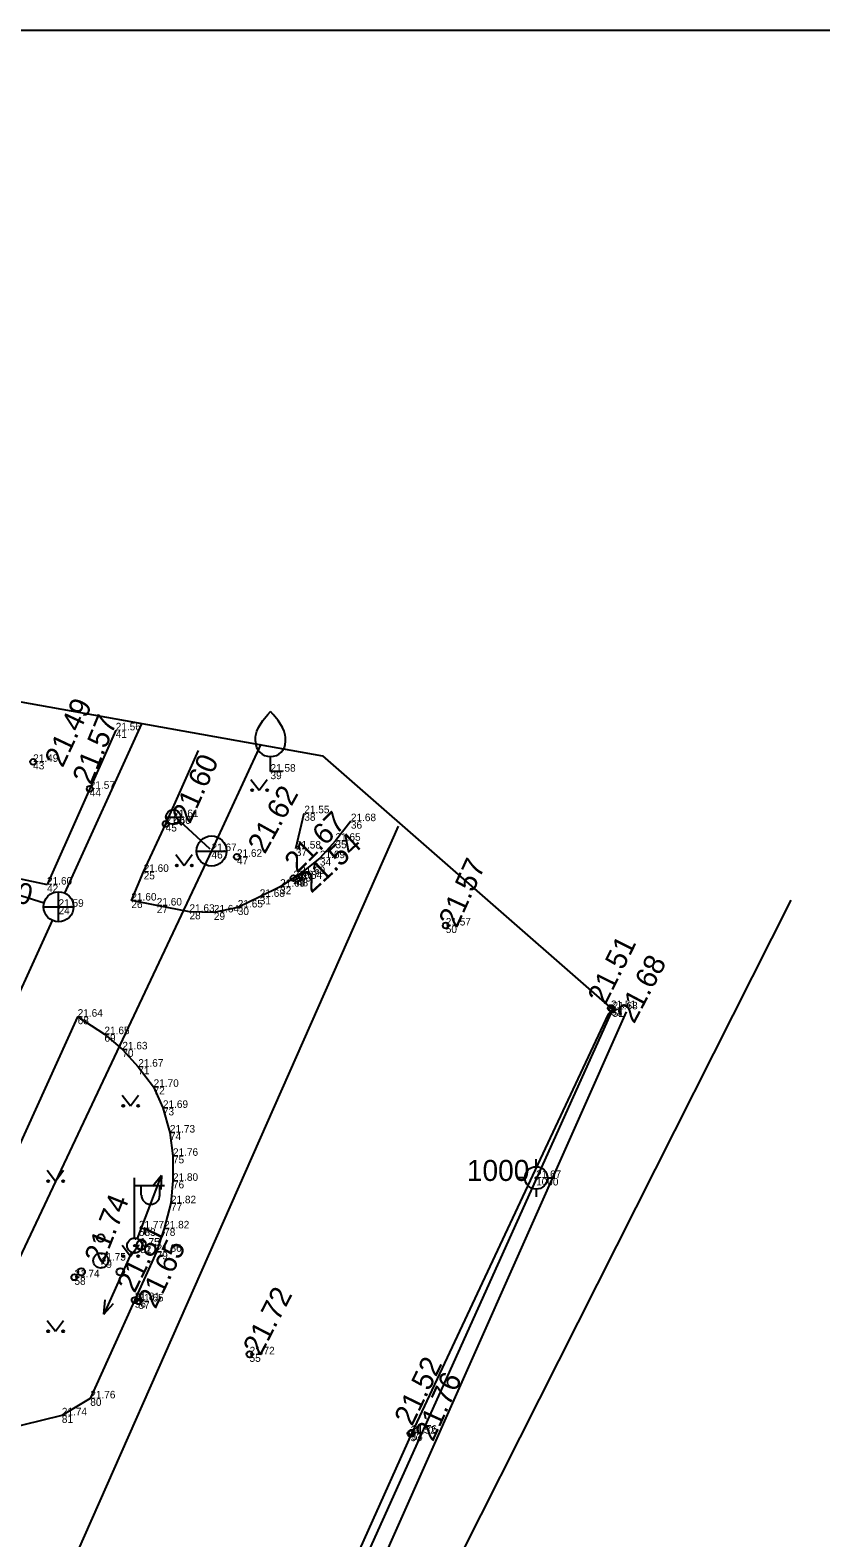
# Model space of a CAD drawing. Extents: x 714279 to 714471, y 6589851 to 6590083.
# Drawn here: x 714408.7 to 714435, y 6590021.5 to 6590071.6 of the extents above; entities that cross this region are included whole.
import ezdxf

# ---------------------------------------------------------------- set-up
doc = ezdxf.new("R2010")
doc.units = 0
for name, color, linetype in [('ALUSVORK', 7, 'Continuous'), ('HALJASTUS', 7, 'Continuous'), ('KKAEV', 7, 'Continuous'), ('KORGUS', 7, 'Continuous'), ('KPKAABEL', 7, 'Continuous'), ('KTRASS', 7, 'Continuous'), ('MOOTKORG', 7, 'Continuous'), ('MOOTMPUNKT', 7, 'Continuous'), ('MOOTPIIR', 7, 'Continuous'), ('MPOHULIIN', 7, 'Continuous'), ('POST', 7, 'Continuous'), ('PUU', 7, 'Continuous'), ('SKTRASS', 7, 'Continuous'), ('TEE', 7, 'Continuous'), ('VKAEV', 7, 'Continuous'), ('VORMISTUS', 7, 'Continuous'), ('VTRASS', 7, 'Continuous')]:
    doc.layers.add(name, color=color, linetype=linetype)

# ---------------------------------------------------------------- blocks, each defined once
blk = doc.blocks.new('KAKAEV')
at = {"layer": 'KKAEV'}
for p, q in [((-1, 0), (1, 0)), ((0, -1), (0, 1))]:
    blk.add_line(p, q, dxfattribs=at)
blk.add_circle((0, 0), 1, dxfattribs=at)
blk = doc.blocks.new('VILJA1')
at = {"layer": 'PUU'}
for p, q in [((0, 0), (0, 1)), ((0.8, 0), (0, 0))]:
    blk.add_line(p, q, dxfattribs=at)
for points in [[(-1, 2), (-1, 2.3), (-0.98, 2.43), (-0.91, 2.69), (-0.79, 2.93), (-0.5, 3.4), (-0.18, 3.81), (0, 4)], [(1, 2), (1, 2.3), (0.98, 2.43), (0.91, 2.69), (0.79, 2.93), (0.5, 3.4), (0.18, 3.81), (0, 4)]]:
    blk.add_lwpolyline(points, dxfattribs=at)
blk.add_arc((0, 2), 1, 180, 0, dxfattribs=at)
blk = doc.blocks.new('VESIIB')
at = {"layer": 'VKAEV'}
for p, q in [((-0.7, 0), (0.7, 0)), ((-0.49, -0.49), (-0.77, -0.77)), ((0.49, -0.49), (0.77, -0.77))]:
    blk.add_line(p, q, dxfattribs=at)
blk.add_circle((0, 0), 0.7, dxfattribs=at)
blk = doc.blocks.new('RING02')
at = {"layer": 'KORGUS'}
blk.add_circle((0, 0), 0.2, dxfattribs=at)
blk = doc.blocks.new('RING02_1')
at = {"layer": 'KORGUS'}
blk.add_circle((0, 0), 0.2, dxfattribs=at)
blk = doc.blocks.new('RING02_2')
at = {"layer": 'KORGUS'}
blk.add_circle((0, 0), 0.2, dxfattribs=at)
blk = doc.blocks.new('PQQSAS')
at = {"layer": 'HALJASTUS'}
for centre, radius in [((0, 1.5), 0.25), ((0, 0), 0.5), ((-1.3, -0.75), 0.25), ((1.3, -0.75), 0.25)]:
    blk.add_circle(centre, radius, dxfattribs=at)
blk = doc.blocks.new('SPYMAR')
at = {"layer": 'ALUSVORK'}
for p, q in [((0, 0.75), (0, 1.25)), ((-0.75, 0), (-1.25, 0)), ((0.75, 0), (1.25, 0)), ((0, -0.75), (0, -1.25))]:
    blk.add_line(p, q, dxfattribs=at)
for radius in [0.75, 0.044]:
    blk.add_circle((0, 0), radius, dxfattribs=at)
blk = doc.blocks.new('BEPOST')
at = {"layer": 'POST'}
for radius in [0.5, 0.0467]:
    blk.add_circle((0, 0), radius, dxfattribs=at)
blk = doc.blocks.new('POINT_DISPLAY')
blk.add_line((0, 0), (0, 0))
blk = doc.blocks.new('VAPOST')
at = {"layer": 'POST'}
for p, q in [((0, 0.5), (0, 4.5)), ((0, 4), (2, 4)), ((0.45, 3.36), (0.45, 4)), ((1.68, 3.36), (1.68, 4))]:
    blk.add_line(p, q, dxfattribs=at)
blk.add_arc((1.07, 3.36), 0.613, 180, 0, dxfattribs=at)
blk.add_blockref('POINT_DISPLAY', (0, 0), dxfattribs=at)
blk = doc.blocks.new('MPSUUN')
at = {"layer": 'MPOHULIIN'}
for p, q in [((0.5, 0), (5, 0)), ((5, 0), (4.1, 0.3)), ((5, 0), (4.1, -0.3))]:
    blk.add_line(p, q, dxfattribs=at)
blk.add_blockref('POINT_DISPLAY', (0, 0), dxfattribs=at)
blk = doc.blocks.new('VEKAEV')
at = {"layer": 'VKAEV'}
blk.add_line((-1, 0), (1, 0), dxfattribs=at)
blk.add_circle((0, 0), 1, dxfattribs=at)
blk = doc.blocks.new('MURU_1')
at = {"layer": 'HALJASTUS'}
for p, q in [((-0.93, 1.21), (0, 0)), ((0, 0), (0.89, 1.21))]:
    blk.add_line(p, q, dxfattribs=at)
for centre in [(-0.8, 0), (0.86, 0)]:
    blk.add_circle(centre, 0.11, dxfattribs=at)

msp = doc.modelspace()

# ---------------------------------------------------------------- linework, layer by layer
at = {"layer": 'HALJASTUS'}
msp.add_lwpolyline([(714417.521, 6590044.411), (714417.803, 6590045.585)], dxfattribs=at)
at = {"layer": 'KPKAABEL'}
msp.add_lwpolyline([(714396.776, 6589958.555), (714410.513, 6589990.138), (714421.117, 6590017.14), (714434.01, 6590042.696)], dxfattribs=at)
at = {"layer": 'KTRASS'}
for points in [[(714409.141, 6590042.598), (714389.491, 6590048.747)], [(714409.831, 6590042.928), (714412.393, 6590048.562)], [(714399.928, 6590021.168), (714409.418, 6590042.018)]]:
    msp.add_lwpolyline(points, dxfattribs=at)
at = {"layer": 'MOOTPIIR'}
msp.add_lwpolyline([(714325.392, 6590064.148), (714418.405, 6590047.495), (714428.059, 6590039.059), (714392.952, 6589961.13), (714372.822, 6589966.903), (714302.696, 6589965.199), (714319.941, 6590042.637), (714325.392, 6590064.148)], dxfattribs=at)
at = {"layer": 'SKTRASS'}
msp.add_lwpolyline([(714419.795, 6590019.325), (714428.522, 6590038.973)], dxfattribs=at)
at = {"layer": 'TEE'}
for points in [[(714333.617, 6590059.437), (714358.94, 6590054.148), (714385.625, 6590048.292), (714406.584, 6590043.775), (714409.241, 6590043.211)], [(714411.528, 6590048.344), (714409.241, 6590043.211)], [(714419.354, 6590045.322), (714418.84, 6590044.67), (714418.323, 6590044.091), (714417.66, 6590043.564), (714416.998, 6590043.14), (714416.32, 6590042.803), (714415.589, 6590042.45), (714414.793, 6590042.284), (714413.981, 6590042.306), (714412.893, 6590042.515), (714412.048, 6590042.68), (714412.457, 6590043.635), (714413.19, 6590045.228), (714414.282, 6590047.669)], [(714428.059, 6590039.059), (714427.912, 6590038.899), (714421.383, 6590024.973), (714411.21, 6590002.295), (714399.51, 6589976.749), (714392.577, 6589961.261), (714392.577, 6589961.261)], [(714404.084, 6590024.922), (714404.084, 6590024.922), (714406.869, 6590031.347), (714410.261, 6590038.815), (714411.152, 6590038.233), (714411.748, 6590037.728), (714412.277, 6590037.152), (714412.789, 6590036.481), (714413.097, 6590035.78), (714413.331, 6590034.96), (714413.433, 6590034.186), (714413.432, 6590033.354), (714413.365, 6590032.606), (714413.139, 6590031.771), (714412.887, 6590030.992), (714410.681, 6590026.115), (714409.734, 6590025.55), (714407.795, 6590025.068), (714405.557, 6590024.814), (714404.758, 6590024.766), (714404.084, 6590024.922)]]:
    msp.add_lwpolyline(points, dxfattribs=at)
at = {"layer": 'VORMISTUS'}
msp.add_lwpolyline([(714471.122, 6589929.143), (714278.622, 6589929.143), (714278.622, 6590071.643), (714471.122, 6590071.643), (714471.122, 6589929.143)], dxfattribs=at)
at = {"layer": 'VTRASS'}
for points in [[(714378.183, 6589965.384), (714401.816, 6590016.993), (714414.734, 6590044.36), (714416.367, 6590047.881)], [(714384.776, 6589963.41), (714420.935, 6590045.157)], [(714414.671, 6590044.392), (714413.506, 6590045.464)]]:
    msp.add_lwpolyline(points, dxfattribs=at)

# ---------------------------------------------------------------- block references
at = {"layer": 'ALUSVORK', "xscale": 0.5, "yscale": 0.5}
msp.add_blockref('SPYMAR', (714425.516, 6590033.449), dxfattribs=at)
at = {"layer": 'HALJASTUS'}
for name, p, xscale, yscale in [('MURU_1', (714416.305, 6590046.349), 0.3, 0.3), ('MURU_1', (714413.805, 6590043.849), 0.3, 0.3), ('MURU_1', (714412.02, 6590035.846), 0.3, 0.3), ('MURU_1', (714409.52, 6590033.346), 0.3, 0.3), ('PQQSAS', (714411.029, 6590030.701), 0.5, 0.5), ('MURU_1', (714412.02, 6590030.846), 0.3, 0.3), ('MURU_1', (714409.52, 6590028.346), 0.3, 0.3)]:
    msp.add_blockref(name, p, dxfattribs=dict(at, xscale=xscale, yscale=yscale))
at = {"layer": 'KKAEV', "xscale": 0.5, "yscale": 0.5}
msp.add_blockref('KAKAEV', (714409.625, 6590042.473), dxfattribs=at)
at = {"layer": 'KORGUS', "xscale": 0.5, "yscale": 0.5}
for name, p in [('RING02', (714408.78, 6590047.294)), ('RING02_1', (714410.664, 6590046.399)), ('RING02_1', (714413.19, 6590045.228)), ('RING02', (714415.562, 6590044.135)), ('RING02_1', (714417.443, 6590043.425)), ('RING02_2', (714417.559, 6590043.402)), ('RING02_1', (714422.511, 6590041.851)), ('RING02_2', (714428.008, 6590039.103)), ('RING02_1', (714428.059, 6590039.059)), ('RING02', (714410.153, 6590030.144)), ('RING02_1', (714412.161, 6590029.384)), ('RING02_2', (714412.284, 6590029.34)), ('RING02_1', (714415.982, 6590027.58)), ('RING02_2', (714421.34, 6590024.941)), ('RING02_1', (714421.383, 6590024.973))]:
    msp.add_blockref(name, p, dxfattribs=at)
at = {"layer": 'MPOHULIIN', "xscale": 0.5, "yscale": 0.5}
for rotation in [69.0021738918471, -114.20796830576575]:
    msp.add_blockref('MPSUUN', (714412.158, 6590031.2), dxfattribs=dict(at, rotation=rotation))
at = {"layer": 'POST', "xscale": 0.5, "yscale": 0.5}
for name, p in [('VAPOST', (714412.152, 6590031.199)), ('BEPOST', (714412.158, 6590031.2))]:
    msp.add_blockref(name, p, dxfattribs=at)
at = {"layer": 'PUU', "xscale": 0.5, "yscale": 0.5}
msp.add_blockref('VILJA1', (714416.678, 6590046.969), dxfattribs=at)
at = {"layer": 'VKAEV'}
for name, p, xscale, yscale in [('VESIIB', (714413.445, 6590045.457), 0.35, 0.35), ('VEKAEV', (714414.715, 6590044.328), 0.5, 0.5)]:
    msp.add_blockref(name, p, dxfattribs=dict(at, xscale=xscale, yscale=yscale))

# ---------------------------------------------------------------- texts
at = {"layer": 'ALUSVORK'}
msp.add_text('1000', height=0.7, dxfattribs=at).set_placement((714423.211, 6590033.349))
at = {"layer": 'KORGUS'}
for s, rotation, p in [('21.49', 64.8075, (714409.762, 6590047.075)), ('21.57', 67.6597, (714410.704, 6590046.502)), ('21.60', 65.6459, (714414.002, 6590045.207)), ('21.62', 60.9549, (714416.491, 6590044.197)), ('21.67', 44.6911, (714417.565, 6590043.565)), ('21.54', 42.6109, (714418.037, 6590042.898)), ('21.57', 65.4183, (714422.879, 6590041.74)), ('21.60', 345.2509, (714406.386, 6590043.102)), ('21.51', 63.572, (714427.824, 6590039.172)), ('21.68', 62.2078, (714428.779, 6590038.554)), ('21.74', 68.1619, (714411.106, 6590030.547)), ('21.81', 63.7346, (714412.158, 6590029.59)), ('21.65', 64.2394, (714412.853, 6590029.06)), ('21.72', 62.6852, (714416.348, 6590027.499)), ('21.52', 64.1023, (714421.39, 6590025.163)), ('21.76', 65.3763, (714422.085, 6590024.644))]:
    msp.add_text(s, height=0.7, rotation=rotation, dxfattribs=at).set_placement(p)
at = {"layer": 'MOOTKORG'}
for s, p in [('21.56', (714411.528, 6590048.344)), ('21.49', (714408.78, 6590047.294)), ('21.58', (714416.678, 6590046.969)), ('21.57', (714410.664, 6590046.399)), ('21.61', (714413.445, 6590045.457)), ('21.55', (714417.803, 6590045.585)), ('21.68', (714419.354, 6590045.322)), ('21.60', (714413.19, 6590045.228)), ('21.67', (714414.715, 6590044.328)), ('21.58', (714417.521, 6590044.411)), ('21.65', (714418.84, 6590044.67)), ('21.62', (714415.562, 6590044.135)), ('21.69', (714418.323, 6590044.091)), ('21.60', (714412.457, 6590043.635)), ('21.67', (714417.443, 6590043.425)), ('21.54', (714417.559, 6590043.402)), ('21.69', (714417.66, 6590043.564)), ('21.60', (714409.241, 6590043.211)), ('21.68', (714416.32, 6590042.803)), ('21.69', (714416.998, 6590043.14)), ('21.59', (714409.625, 6590042.473)), ('21.60', (714412.048, 6590042.68)), ('21.60', (714412.893, 6590042.515)), ('21.63', (714413.981, 6590042.306)), ('21.65', (714415.589, 6590042.45)), ('21.64', (714414.793, 6590042.284)), ('21.57', (714422.511, 6590041.851)), ('21.64', (714410.261, 6590038.815)), ('21.51', (714428.008, 6590039.103)), ('21.68', (714428.059, 6590039.059)), ('21.65', (714411.152, 6590038.233)), ('21.63', (714411.748, 6590037.728)), ('21.67', (714412.277, 6590037.152)), ('21.70', (714412.789, 6590036.481)), ('21.69', (714413.097, 6590035.78)), ('21.73', (714413.331, 6590034.96)), ('21.76', (714413.433, 6590034.186)), ('21.80', (714413.432, 6590033.354)), ('21.67', (714425.516, 6590033.449)), ('21.82', (714413.365, 6590032.606)), ('21.77', (714412.299, 6590031.771)), ('21.82', (714413.139, 6590031.771)), ('21.75', (714412.152, 6590031.199)), ('21.75', (714412.158, 6590031.2)), ('21.86', (714412.887, 6590030.992)), ('21.75', (714411.029, 6590030.701)), ('21.74', (714410.153, 6590030.144)), ('21.81', (714412.161, 6590029.384)), ('21.65', (714412.284, 6590029.34)), ('21.72', (714415.982, 6590027.58)), ('21.76', (714410.681, 6590026.115)), ('21.74', (714409.734, 6590025.55)), ('21.52', (714421.34, 6590024.941)), ('21.76', (714421.383, 6590024.973))]:
    msp.add_text(s, height=0.25, dxfattribs=at).set_placement(p)
at = {"layer": 'MOOTMPUNKT'}
for s, p in [('41', (714411.528, 6590048.094)), ('43', (714408.78, 6590047.044)), ('39', (714416.678, 6590046.719)), ('44', (714410.664, 6590046.149)), ('38', (714417.803, 6590045.335)), ('45', (714413.19, 6590044.978)), ('40', (714413.445, 6590045.207)), ('36', (714419.354, 6590045.072)), ('35', (714418.84, 6590044.42)), ('46', (714414.715, 6590044.078)), ('47', (714415.562, 6590043.885)), ('37', (714417.521, 6590044.161)), ('34', (714418.323, 6590043.841)), ('25', (714412.457, 6590043.385)), ('33', (714417.66, 6590043.314)), ('42', (714409.241, 6590042.961)), ('32', (714416.998, 6590042.89)), ('49', (714417.443, 6590043.175)), ('48', (714417.559, 6590043.152)), ('26', (714412.048, 6590042.43)), ('31', (714416.32, 6590042.553)), ('24', (714409.625, 6590042.223)), ('27', (714412.893, 6590042.265)), ('28', (714413.981, 6590042.056)), ('29', (714414.793, 6590042.034)), ('30', (714415.589, 6590042.2)), ('50', (714422.511, 6590041.601)), ('52', (714428.008, 6590038.853)), ('51', (714428.059, 6590038.809)), ('68', (714410.261, 6590038.565)), ('69', (714411.152, 6590037.983)), ('70', (714411.748, 6590037.478)), ('71', (714412.277, 6590036.902)), ('72', (714412.789, 6590036.231)), ('73', (714413.097, 6590035.53)), ('74', (714413.331, 6590034.71)), ('75', (714413.433, 6590033.936)), ('76', (714413.432, 6590033.104)), ('1000', (714425.516, 6590033.199)), ('77', (714413.365, 6590032.356)), ('583', (714412.299, 6590031.521)), ('78', (714413.139, 6590031.521)), ('582', (714412.152, 6590030.949)), ('581', (714412.158, 6590030.95)), ('59', (714411.029, 6590030.451)), ('79', (714412.887, 6590030.742)), ('58', (714410.153, 6590029.894)), ('56', (714412.161, 6590029.134)), ('57', (714412.284, 6590029.09)), ('55', (714415.982, 6590027.33)), ('80', (714410.681, 6590025.865)), ('81', (714409.734, 6590025.3)), ('53', (714421.34, 6590024.691)), ('54', (714421.383, 6590024.723))]:
    msp.add_text(s, height=0.25, dxfattribs=at).set_placement(p)

doc.saveas('drawing.dxf')
